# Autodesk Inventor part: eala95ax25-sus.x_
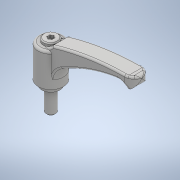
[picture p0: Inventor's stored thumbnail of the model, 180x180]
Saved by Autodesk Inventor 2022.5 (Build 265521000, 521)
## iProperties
Created: 2018-05
Part Number: eala95ax25-sus.x_
Material: 一般
Document SubType Name: Modeling
Designer: imaocorp
Density: 1 g/cm^3
Appearance: 既定
Sending System: SOLIDWORKS 2016-2016286
MC: AMD64
MC_MODEL: AMD64 Family 21 Model 2 Stepping 0, AuthenticAMD
OS: Windows_NT
FRU: Parasolid Version 28.0, build 224,  7-29-2016
FORMAT: text
GUISE: transmit
KEY: eala95ax25-sus
FILE: eala95ax25-sus.x_t
DATE: Fri May 18 11:33:00 2018
Author: imaocorp
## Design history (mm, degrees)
feature "Base1"
node "ソリッド1"
